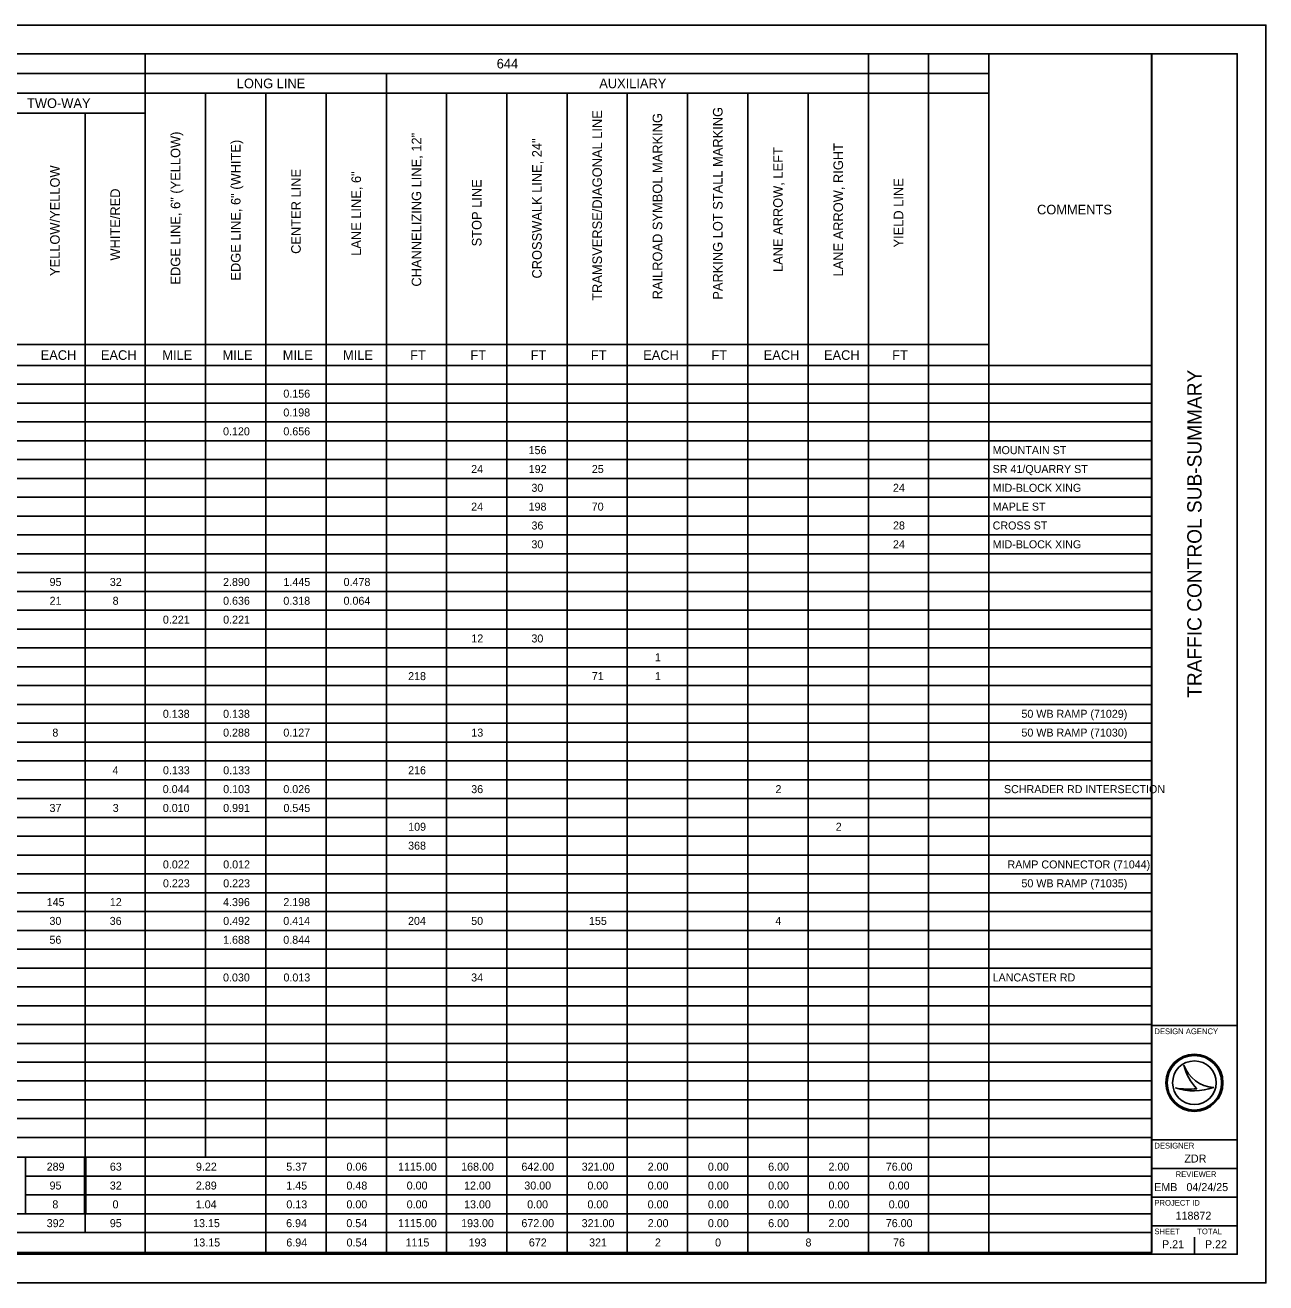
# Model space of a CAD drawing. Extents: x 0 to 34, y 0 to 22.
# Drawn here: x 12.29 to 34, y 0 to 22 of the extents above; entities that cross this region are included whole.
import ezdxf

# ---------------------------------------------------------------- set-up
doc = ezdxf.new("R2010")
doc.units = 0
for name, color, linetype in [('SH_Border', 7, 'Continuous'), ('SH_Cut_Line', 7, 'Continuous'), ('SH_Data', 7, 'Continuous'), ('SH_Text', 7, 'Continuous')]:
    doc.layers.add(name, color=color, linetype=linetype)

msp = doc.modelspace()

# ---------------------------------------------------------------- linework, layer by layer
at = {"layer": 'SH_Border'}
for p, q in [((32, 0.5), (32, 21.5)), ((32, 4.5), (33.5, 4.5)), ((32, 2.5), (33.5, 2.5)), ((32, 2), (33.5, 2)), ((32, 1.5), (33.5, 1.5)), ((32, 1), (33.5, 1))]:
    msp.add_line(p, q, dxfattribs=at)
msp.add_lwpolyline([(1.5, 21.5), (33.5, 21.5), (33.5, 0.5), (1.5, 0.5)], close=True, dxfattribs=at)
at = {"layer": 'SH_Cut_Line'}
msp.add_lwpolyline([(0, 0), (34, 0), (34, 22), (0, 22)], close=True, dxfattribs=at)
at = {"layer": 'SH_Data'}
for p, q in [((32.567, 3.81), (32.567, 3.81)), ((32.417, 3.41), (32.417, 3.41)), ((32.75, 3.5), (32.75, 3.5)), ((33.087, 3.419), (33.087, 3.419)), ((32.375, 0.675), (32.375, 0.675)), ((32.75, 0.5), (32.75, 0.8))]:
    msp.add_line(p, q, dxfattribs=at)
for radius in [0.5, 0.477, 0.477, 0.382]:
    msp.add_circle((32.75, 3.5), radius, dxfattribs=at)
for centre, radius, start, end in [((33.116, 3.998), 0.58, 198.9257, 198.9319), ((33.347, 3.97), 0.796, 191.6379, 191.6421), ((33.116, 3.998), 0.58, 198.9319, 267.1657), ((33.347, 3.97), 0.796, 191.6421, 226.0947), ((32.739, 4.37), 1.013, 251.4576, 290.0832), ((32.648, 4.654), 1.266, 259.4964, 259.4995), ((32.739, 4.37), 1.013, 251.4527, 251.4576), ((32.648, 4.654), 1.266, 259.4995, 276.6672)]:
    msp.add_arc(centre, radius, start, end, dxfattribs=at)
at = {"layer": 'SH_Text'}
for p, q in [((8.061, 21.5), (32.004, 21.5)), ((14.396, 21.5), (14.396, 0.533)), ((27.046, 21.5), (27.046, 0.533)), ((28.1, 21.5), (28.1, 0.533)), ((29.154, 21.5), (29.154, 0.533)), ((32.004, 21.5), (32.004, 0.533)), ((8.083, 21.154), (29.154, 21.154)), ((18.613, 21.154), (18.613, 0.533)), ((9.126, 20.808), (29.154, 20.808)), ((15.451, 20.808), (15.451, 2.196)), ((16.505, 20.808), (16.505, 0.533)), ((17.559, 20.808), (17.559, 0.533)), ((19.667, 20.808), (19.667, 0.533)), ((20.721, 20.808), (20.721, 0.533)), ((21.775, 20.808), (21.775, 0.533)), ((22.829, 20.808), (22.829, 0.533)), ((23.884, 20.808), (23.884, 0.533)), ((24.938, 20.808), (24.938, 0.533)), ((25.992, 20.808), (25.992, 0.879)), ((9.126, 20.462), (14.396, 20.462)), ((13.342, 20.462), (13.342, 2.196)), ((8.083, 16.411), (29.154, 16.411)), ((8.083, 16.048), (32.004, 16.048)), ((8.083, 15.719), (32.004, 15.719)), ((8.083, 15.389), (32.004, 15.389)), ((8.083, 15.06), (32.004, 15.06)), ((8.083, 14.731), (32.004, 14.731)), ((8.083, 14.401), (32.004, 14.401)), ((8.083, 14.072), (32.004, 14.072)), ((8.083, 13.742), (32.004, 13.742)), ((8.083, 13.413), (32.004, 13.413)), ((8.083, 13.084), (32.004, 13.084)), ((8.083, 12.754), (32.004, 12.754)), ((8.083, 12.425), (32.004, 12.425)), ((8.083, 12.095), (32.004, 12.095)), ((8.083, 11.766), (32.004, 11.766)), ((8.083, 11.436), (32.004, 11.436)), ((8.083, 11.107), (32.004, 11.107)), ((8.083, 10.778), (32.004, 10.778)), ((8.083, 10.448), (32.004, 10.448)), ((8.083, 10.119), (32.004, 10.119)), ((8.083, 9.789), (32.004, 9.789)), ((8.083, 9.46), (32.004, 9.46)), ((8.083, 9.131), (32.004, 9.131)), ((8.083, 8.801), (32.004, 8.801)), ((8.083, 8.472), (32.004, 8.472)), ((8.083, 8.142), (32.004, 8.142)), ((8.083, 7.813), (32.004, 7.813)), ((8.083, 7.484), (32.004, 7.484)), ((8.083, 7.154), (32.004, 7.154)), ((8.083, 6.825), (32.004, 6.825)), ((8.083, 6.495), (32.004, 6.495)), ((8.083, 6.166), (32.004, 6.166)), ((8.083, 5.836), (32.004, 5.836)), ((8.083, 5.507), (32.004, 5.507)), ((8.083, 5.178), (32.004, 5.178)), ((8.083, 4.848), (32.004, 4.848)), ((8.083, 4.519), (32.004, 4.519)), ((8.083, 4.189), (32.004, 4.189)), ((8.083, 3.86), (32.004, 3.86)), ((8.083, 3.531), (32.004, 3.531)), ((8.083, 3.201), (32.004, 3.201)), ((8.083, 2.872), (32.004, 2.872)), ((8.083, 2.542), (32.004, 2.542)), ((8.083, 2.196), (32.004, 2.196)), ((12.299, 2.196), (12.299, 1.208)), ((13.331, 2.196), (13.331, 1.208)), ((13.353, 2.196), (13.353, 1.208)), ((12.299, 1.867), (13.331, 1.867)), ((13.353, 1.867), (32.004, 1.867)), ((12.299, 1.538), (13.331, 1.538)), ((13.353, 1.538), (32.004, 1.538)), ((8.083, 1.208), (32.004, 1.208)), ((13.342, 1.208), (13.342, 0.879)), ((8.083, 0.879), (32.004, 0.879)), ((8.061, 0.533), (32.004, 0.533))]:
    msp.add_line(p, q, dxfattribs=at)

# ---------------------------------------------------------------- texts
at = {"layer": 'SH_Data'}
msp.add_text('TRAFFIC CONTROL SUB-SUMMARY', height=0.25, rotation=90, dxfattribs=at).set_placement((32.875, 10.234))
for s, height, p in [('DESIGN AGENCY', 0.1, (32.05, 4.35)), ('DESIGNER', 0.1, (32.05, 2.35)), ('ZDR', 0.14, (32.575, 2.105)), ('REVIEWER', 0.1, (32.422, 1.85)), ('EMB', 0.14, (32.047, 1.605)), ('04/24/25', 0.14, (32.611, 1.605)), ('PROJECT ID', 0.1, (32.05, 1.35)), ('118872', 0.14, (32.421, 1.105)), ('SHEET', 0.1, (32.05, 0.85)), ('TOTAL', 0.1, (32.8, 0.85)), ('P.21', 0.14, (32.184, 0.605)), ('P.22', 0.14, (32.935, 0.605))]:
    msp.add_text(s, height=height, dxfattribs=at).set_placement(p)
at = {"layer": 'SH_Text'}
for s, height, p in [('644', 0.168, (20.544, 21.243)), ('LONG LINE', 0.168, (15.996, 20.897)), ('AUXILIARY', 0.168, (22.338, 20.897)), ('TWO-WAY', 0.168, (12.327, 20.551)), ('COMMENTS', 0.168, (29.997, 18.69)), ('EACH', 0.168, (12.565, 16.145)), ('EACH', 0.168, (13.619, 16.145)), ('MILE', 0.168, (14.693, 16.145)), ('MILE', 0.168, (15.747, 16.145)), ('MILE', 0.168, (16.801, 16.145)), ('MILE', 0.168, (17.855, 16.145)), ('FT', 0.168, (19.029, 16.145)), ('FT', 0.168, (20.083, 16.145)), ('FT', 0.168, (21.137, 16.145)), ('FT', 0.168, (22.191, 16.145)), ('EACH', 0.168, (23.106, 16.145)), ('FT', 0.168, (24.299, 16.145)), ('EACH', 0.168, (25.215, 16.145)), ('EACH', 0.168, (26.269, 16.145)), ('FT', 0.168, (27.462, 16.145)), ('0.156', 0.14, (16.811, 15.484)), ('0.198', 0.14, (16.811, 15.155)), ('0.120', 0.14, (15.756, 14.825)), ('0.656', 0.14, (16.811, 14.825)), ('156', 0.14, (21.102, 14.496)), ('MOUNTAIN ST', 0.14, (29.22, 14.496)), ('24', 0.14, (20.097, 14.166)), ('192', 0.14, (21.104, 14.166)), ('25', 0.14, (22.208, 14.166)), ('SR 41/QUARRY ST', 0.14, (29.22, 14.166)), ('30', 0.14, (21.151, 13.837)), ('24', 0.14, (27.476, 13.837)), ('MID-BLOCK XING', 0.14, (29.22, 13.837)), ('24', 0.14, (20.097, 13.508)), ('198', 0.14, (21.102, 13.508)), ('70', 0.14, (22.206, 13.508)), ('MAPLE ST', 0.14, (29.22, 13.508)), ('36', 0.14, (21.152, 13.178)), ('28', 0.14, (27.477, 13.178)), ('CROSS ST', 0.14, (29.22, 13.178)), ('30', 0.14, (21.151, 12.849)), ('24', 0.14, (27.476, 12.849)), ('MID-BLOCK XING', 0.14, (29.22, 12.849)), ('95', 0.14, (12.721, 12.19)), ('32', 0.14, (13.775, 12.19)), ('2.890', 0.14, (15.756, 12.19)), ('1.445', 0.14, (16.813, 12.19)), ('0.478', 0.14, (17.865, 12.19)), ('21', 0.14, (12.721, 11.861)), ('8', 0.14, (13.824, 11.861)), ('0.636', 0.14, (15.757, 11.861)), ('0.318', 0.14, (16.811, 11.861)), ('0.064', 0.14, (17.864, 11.861)), ('0.221', 0.14, (14.704, 11.531)), ('0.221', 0.14, (15.758, 11.531)), ('12', 0.14, (20.1, 11.202)), ('30', 0.14, (21.151, 11.202)), ('1', 0.14, (23.312, 10.872)), ('218', 0.14, (18.994, 10.543)), ('71', 0.14, (22.208, 10.543)), ('1', 0.14, (23.312, 10.543)), ('0.138', 0.14, (14.703, 9.884)), ('0.138', 0.14, (15.757, 9.884)), ('50 WB RAMP (71029)', 0.14, (29.724, 9.884)), ('8', 0.14, (12.77, 9.555)), ('0.288', 0.14, (15.757, 9.555)), ('0.127', 0.14, (16.811, 9.555)), ('13', 0.14, (20.1, 9.555)), ('50 WB RAMP (71030)', 0.14, (29.724, 9.555)), ('4', 0.14, (13.822, 8.896)), ('0.133', 0.14, (14.705, 8.896)), ('0.133', 0.14, (15.759, 8.896)), ('216', 0.14, (18.994, 8.896)), ('0.044', 0.14, (14.701, 8.566)), ('0.103', 0.14, (15.759, 8.566)), ('0.026', 0.14, (16.811, 8.566)), ('36', 0.14, (20.098, 8.566)), ('2', 0.14, (25.421, 8.566)), ('SCHRADER RD INTERSECTION', 0.14, (29.418, 8.566)), ('37', 0.14, (12.72, 8.237)), ('3', 0.14, (13.826, 8.237)), ('0.010', 0.14, (14.702, 8.237)), ('0.991', 0.14, (15.758, 8.237)), ('0.545', 0.14, (16.813, 8.237)), ('109', 0.14, (18.995, 7.908)), ('2', 0.14, (26.475, 7.908)), ('368', 0.14, (18.994, 7.578)), ('0.022', 0.14, (14.704, 7.249)), ('0.012', 0.14, (15.759, 7.249)), ('RAMP CONNECTOR (71044)', 0.14, (29.48, 7.249)), ('0.223', 0.14, (14.705, 6.919)), ('0.223', 0.14, (15.759, 6.919)), ('50 WB RAMP (71035)', 0.14, (29.724, 6.919)), ('145', 0.14, (12.671, 6.59)), ('12', 0.14, (13.775, 6.59)), ('4.396', 0.14, (15.757, 6.59)), ('2.198', 0.14, (16.811, 6.59)), ('30', 0.14, (12.719, 6.261)), ('36', 0.14, (13.773, 6.261)), ('0.492', 0.14, (15.759, 6.261)), ('0.414', 0.14, (16.81, 6.261)), ('204', 0.14, (18.992, 6.261)), ('50', 0.14, (20.097, 6.261)), ('155', 0.14, (22.158, 6.261)), ('4', 0.14, (25.418, 6.261)), ('56', 0.14, (12.719, 5.931)), ('1.688', 0.14, (15.757, 5.931)), ('0.844', 0.14, (16.81, 5.931)), ('0.030', 0.14, (15.756, 5.272)), ('0.013', 0.14, (16.813, 5.272)), ('34', 0.14, (20.097, 5.272)), ('LANCASTER RD', 0.14, (29.22, 5.272)), ('289', 0.14, (12.67, 1.962)), ('63', 0.14, (13.776, 1.962)), ('9.22', 0.14, (15.282, 1.962)), ('5.37', 0.14, (16.862, 1.962)), ('0.06', 0.14, (17.915, 1.962)), ('1115.00', 0.14, (18.818, 1.962)), ('168.00', 0.14, (19.922, 1.962)), ('642.00', 0.14, (20.976, 1.962)), ('321.00', 0.14, (22.03, 1.962)), ('2.00', 0.14, (23.185, 1.962)), ('0.00', 0.14, (24.239, 1.962)), ('6.00', 0.14, (25.293, 1.962)), ('2.00', 0.14, (26.348, 1.962)), ('76.00', 0.14, (27.351, 1.962)), ('95', 0.14, (12.721, 1.632)), ('32', 0.14, (13.775, 1.632)), ('2.89', 0.14, (15.281, 1.632)), ('1.45', 0.14, (16.863, 1.632)), ('0.48', 0.14, (17.915, 1.632)), ('0.00', 0.14, (18.969, 1.632)), ('12.00', 0.14, (19.973, 1.632)), ('30.00', 0.14, (21.027, 1.632)), ('0.00', 0.14, (22.131, 1.632)), ('0.00', 0.14, (23.185, 1.632)), ('0.00', 0.14, (24.239, 1.632)), ('0.00', 0.14, (25.293, 1.632)), ('0.00', 0.14, (26.348, 1.632)), ('0.00', 0.14, (27.402, 1.632)), ('8', 0.14, (12.77, 1.303)), ('0', 0.14, (13.823, 1.303)), ('1.04', 0.14, (15.279, 1.303)), ('0.13', 0.14, (16.864, 1.303)), ('0.00', 0.14, (17.915, 1.303)), ('0.00', 0.14, (18.969, 1.303)), ('13.00', 0.14, (19.973, 1.303)), ('0.00', 0.14, (21.077, 1.303)), ('0.00', 0.14, (22.131, 1.303)), ('0.00', 0.14, (23.185, 1.303)), ('0.00', 0.14, (24.239, 1.303)), ('0.00', 0.14, (25.293, 1.303)), ('0.00', 0.14, (26.348, 1.303)), ('0.00', 0.14, (27.402, 1.303)), ('392', 0.14, (12.671, 0.974)), ('95', 0.14, (13.775, 0.974)), ('13.15', 0.14, (15.232, 0.974)), ('6.94', 0.14, (16.86, 0.974)), ('0.54', 0.14, (17.914, 0.974)), ('1115.00', 0.14, (18.818, 0.974)), ('193.00', 0.14, (19.922, 0.974)), ('672.00', 0.14, (20.976, 0.974)), ('321.00', 0.14, (22.03, 0.974)), ('2.00', 0.14, (23.185, 0.974)), ('0.00', 0.14, (24.239, 0.974)), ('6.00', 0.14, (25.293, 0.974)), ('2.00', 0.14, (26.348, 0.974)), ('76.00', 0.14, (27.351, 0.974)), ('13.15', 0.14, (15.236, 0.636)), ('6.94', 0.14, (16.863, 0.636)), ('0.54', 0.14, (17.917, 0.636)), ('1115', 0.14, (18.949, 0.636)), ('193', 0.14, (20.052, 0.636)), ('672', 0.14, (21.106, 0.636)), ('321', 0.14, (22.16, 0.636)), ('2', 0.14, (23.312, 0.636)), ('0', 0.14, (24.364, 0.636)), ('8', 0.14, (25.946, 0.636)), ('76', 0.14, (27.478, 0.636))]:
    msp.add_text(s, height=height, dxfattribs=at).set_placement(p)
for s, p in [('TRAMSVERSE/DIAGONAL LINE', (22.386, 17.179)), ('PARKING LOT STALL MARKING', (24.495, 17.198)), ('RAILROAD SYMBOL MARKING', (23.44, 17.204)), ('EDGE LINE, 6" (YELLOW)', (15.008, 17.462)), ('CHANNELIZING LINE, 12"', (19.224, 17.427)), ('EDGE LINE, 6" (WHITE)', (16.062, 17.531)), ('CROSSWALK LINE, 24"', (21.332, 17.568)), ('LANE ARROW, LEFT', (25.549, 17.681)), ('LANE ARROW, RIGHT', (26.603, 17.603)), ('YELLOW/YELLOW', (12.899, 17.612)), ('CENTER LINE', (17.116, 17.999)), ('LANE LINE, 6"', (18.17, 17.965)), ('STOP LINE', (20.278, 18.13)), ('YIELD LINE', (27.657, 18.111)), ('WHITE/RED', (13.953, 17.882))]:
    msp.add_text(s, height=0.168, rotation=90, dxfattribs=at).set_placement(p)

doc.saveas('drawing.dxf')
